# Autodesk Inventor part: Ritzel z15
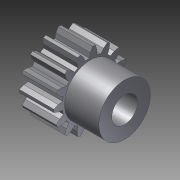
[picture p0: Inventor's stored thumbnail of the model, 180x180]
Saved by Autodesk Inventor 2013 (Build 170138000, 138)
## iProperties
Created: 2012-07
Part Number: Ritzel z15
Material: Stahl
Document SubType Name: Modeling
Designer: rYan
Mass: 1.81106 g
Surface Area: 4.00076 cm^2
Volume: 0.230709 cm^3
Density: 7.85 g/cm^3
Übersetzungsnorm: STEP AP214IS
Dateiname: c:/PPEXPORT/antriebselemente_und_normteile/stirnzahnraeder/stirnzahnraeder_stahl/modul_05_und_07/artikel_nr___21101500.stp
Postprozessor: Build: 138, Release: 2013 RTM - Date: Thu 03/01/2012
Gesendete Einheiten: Millimeter
Unbestimmtheit: 1.0000000000000002e-06
Author: rYan
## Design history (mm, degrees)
node "11"
node "1"
node "Basis1"
